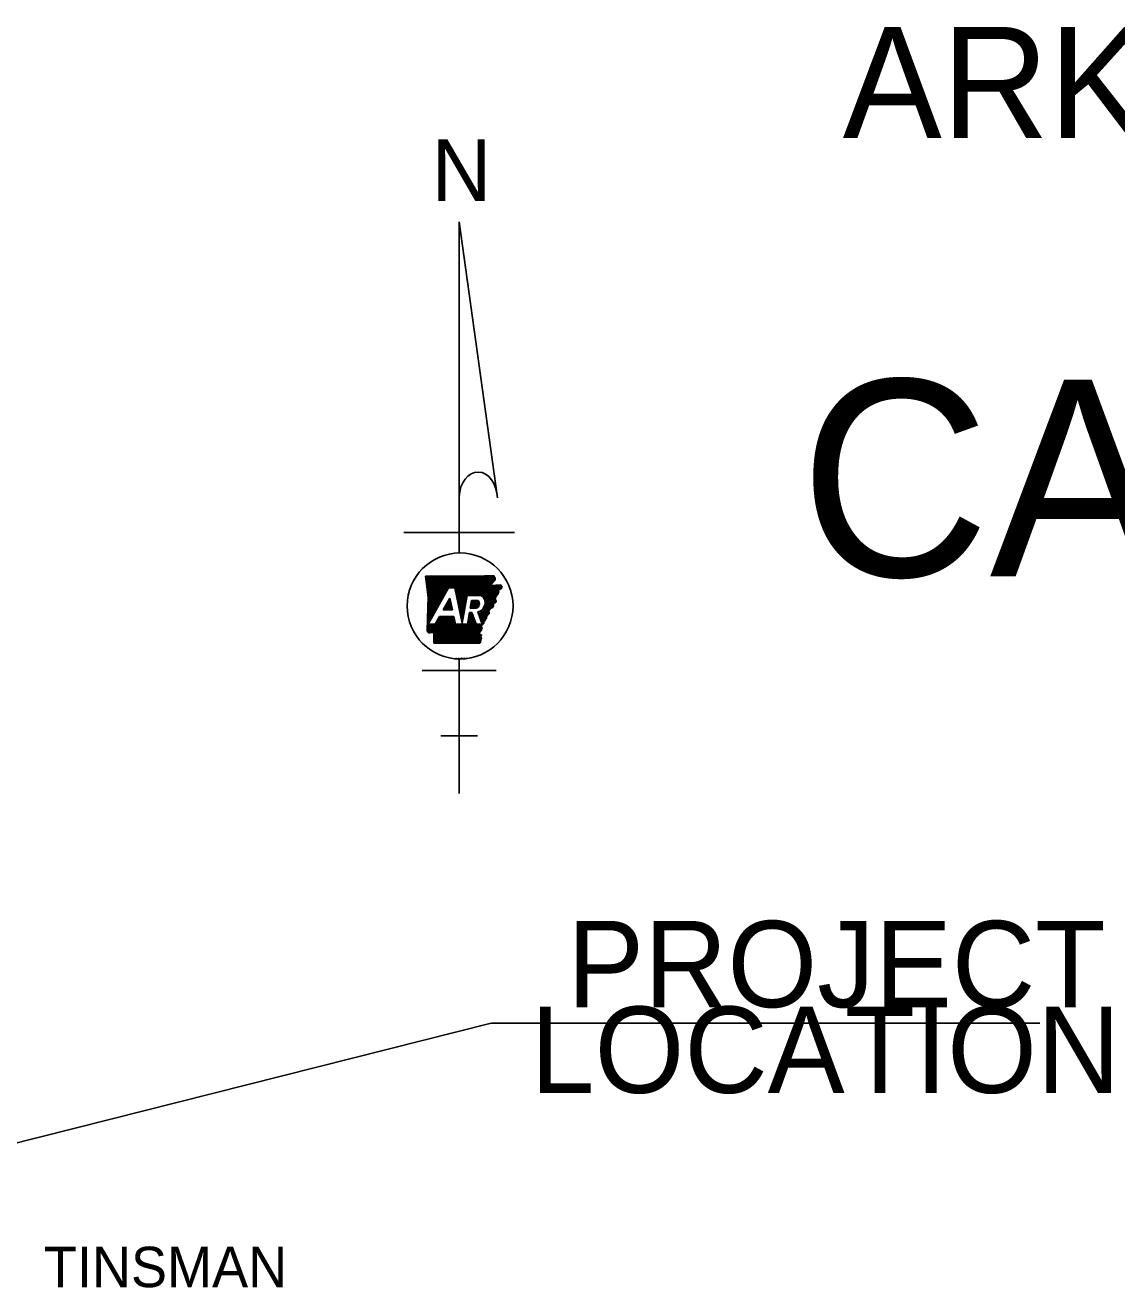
# Model space of a CAD drawing. Extents: x 172 to 3385, y 73 to 2074.
# Drawn here: x 834 to 1267, y 1573 to 2074 of the extents above; entities that cross this region are included whole.
import ezdxf

# ---------------------------------------------------------------- set-up
doc = ezdxf.new("R2010")
doc.units = 0
for name, color, linetype in [('Default', 7, 'Continuous'), ('G-ANNO-NPLT', 7, 'Continuous'), ('R_Border', 7, 'Continuous'), ('R_Border Prem', 7, 'Continuous')]:
    doc.layers.add(name, color=color, linetype=linetype)

msp = doc.modelspace()

# ---------------------------------------------------------------- linework, layer by layer
at = {"layer": 'Default'}
for p, q in [((1005.88, 1996.26), (1021.04, 1886.7)), ((1005.88, 1864.88), (1005.88, 1996.26)), ((983.94, 1873), (1027.81, 1873)), ((992.57, 1855.46), (992.75, 1855.64)), ((992.63, 1854.95), (993.33, 1855.64)), ((992.7, 1854.43), (993.91, 1855.64)), ((992.76, 1853.91), (994.49, 1855.64)), ((992.82, 1853.4), (995.07, 1855.64)), ((992.89, 1852.88), (995.65, 1855.64)), ((992.95, 1852.37), (996.23, 1855.64)), ((993.02, 1851.85), (996.81, 1855.64)), ((993.08, 1851.33), (997.39, 1855.64)), ((993.15, 1850.82), (997.97, 1855.64)), ((993.21, 1850.3), (998.55, 1855.64)), ((993.27, 1849.78), (999.13, 1855.64)), ((993.34, 1849.27), (999.71, 1855.64)), ((993.4, 1848.75), (1000.29, 1855.64)), ((993.42, 1842.96), (1006.11, 1855.65)), ((993.44, 1843.56), (1005.53, 1855.65)), ((993.46, 1844.16), (1004.95, 1855.65)), ((993.47, 1848.23), (1000.87, 1855.64)), ((993.48, 1844.76), (1004.37, 1855.65)), ((993.5, 1845.37), (1003.78, 1855.65)), ((993.52, 1845.97), (1003.2, 1855.65)), ((993.53, 1847.72), (1001.46, 1855.64)), ((993.54, 1846.57), (1002.62, 1855.64)), ((993.56, 1847.17), (1002.04, 1855.64)), ((1002.05, 1851.01), (1006.69, 1855.65)), ((1002.63, 1851.01), (1007.28, 1855.65)), ((1003.21, 1851.01), (1007.86, 1855.66)), ((1003.79, 1851.01), (1008.45, 1855.67)), ((1004.15, 1850.79), (1009.04, 1855.68)), ((1004.25, 1850.31), (1009.63, 1855.69)), ((1004.36, 1849.83), (1010.22, 1855.7)), ((1004.46, 1849.35), (1010.81, 1855.7)), ((1004.56, 1848.87), (1011.4, 1855.71)), ((1004.66, 1848.39), (1011.99, 1855.72)), ((1004.76, 1847.92), (1012.58, 1855.73)), ((1004.87, 1847.44), (1013.17, 1855.74)), ((1004.97, 1846.96), (1013.76, 1855.75)), ((1005.07, 1846.48), (1014.35, 1855.76)), ((1005.17, 1846), (1014.94, 1855.77)), ((1005.28, 1845.52), (1015.53, 1855.78)), ((1005.38, 1845.05), (1016.12, 1855.79)), ((1005.48, 1844.57), (1016.72, 1855.8)), ((1009.52, 1848.02), (1017.31, 1855.82)), ((1010.1, 1848.02), (1017.91, 1855.83)), ((1010.68, 1848.02), (1018.5, 1855.84)), ((1011.26, 1848.02), (1019.09, 1855.86)), ((1011.84, 1848.02), (1019.69, 1855.87)), ((1012.42, 1848.02), (1019.82, 1855.42)), ((1013, 1848.02), (1020.1, 1855.12)), ((1013.58, 1848.02), (1020.17, 1854.61)), ((993.38, 1841.76), (1000.48, 1848.86)), ((993.4, 1842.36), (1001.24, 1850.2)), ((993.6, 1836.7), (1001.7, 1851.01)), ((1001.7, 1851.01), (1004.1, 1851.01)), ((1008.99, 1848.02), (1014.62, 1848.02)), ((1014.16, 1848.02), (1018.85, 1852.71)), ((1014.69, 1847.97), (1018.73, 1852.01)), ((1015.01, 1847.7), (1019.35, 1852.04)), ((1015.29, 1847.41), (1019.96, 1852.08)), ((1015.54, 1847.08), (1020.57, 1852.11)), ((1015.76, 1846.71), (1021.18, 1852.14)), ((1015.93, 1846.31), (1021.8, 1852.17)), ((1016.03, 1844.08), (1021.3, 1849.35)), ((1016.07, 1845.86), (1022.35, 1852.14)), ((1016.15, 1845.36), (1022.62, 1851.83)), ((1016.15, 1844.78), (1021.23, 1849.86)), ((1020.65, 1848.12), (1021.37, 1848.84)), ((1022.36, 1850.99), (1022.89, 1851.52)), ((993.3, 1839.36), (997.45, 1843.5)), ((993.32, 1839.96), (998.21, 1844.84)), ((993.34, 1840.56), (998.96, 1846.18)), ((993.36, 1841.16), (999.72, 1847.52)), ((999.55, 1842.31), (1002.2, 1846.99)), ((999.58, 1842.31), (1002.57, 1845.3)), ((1000.16, 1842.31), (1002.67, 1844.82)), ((1000.28, 1843.59), (1002.46, 1845.78)), ((1000.74, 1842.31), (1002.77, 1844.34)), ((1001.03, 1844.93), (1002.36, 1846.26)), ((1001.33, 1842.31), (1002.87, 1843.86)), ((1001.79, 1846.27), (1002.26, 1846.73)), ((1001.91, 1842.31), (1002.98, 1843.39)), ((1002.49, 1842.31), (1003.08, 1842.91)), ((1005.58, 1844.09), (1008.88, 1847.38)), ((1005.69, 1843.61), (1008.76, 1846.68)), ((1005.79, 1843.13), (1008.63, 1845.98)), ((1005.89, 1842.65), (1008.51, 1845.27)), ((1005.99, 1842.18), (1008.39, 1844.57)), ((1006.1, 1841.7), (1008.27, 1843.87)), ((1006.2, 1841.22), (1008.14, 1843.16)), ((1010.21, 1842.95), (1013.27, 1846)), ((1010.21, 1842.95), (1012.62, 1842.95)), ((1010.33, 1843.65), (1012.69, 1846)), ((1010.46, 1844.35), (1012.11, 1846)), ((1010.58, 1845.05), (1011.53, 1846)), ((1010.7, 1845.76), (1010.95, 1846)), ((1010.74, 1846), (1013.39, 1846)), ((1010.8, 1842.95), (1013.59, 1845.74)), ((1011.38, 1842.95), (1013.79, 1845.36)), ((1011.96, 1842.95), (1013.9, 1844.89)), ((1012.54, 1842.95), (1013.85, 1844.26)), ((1013.63, 1840.52), (1020.07, 1846.96)), ((1013.79, 1840.1), (1020.18, 1846.49)), ((1013.94, 1839.67), (1020.29, 1846.01)), ((1014.1, 1839.25), (1020.39, 1845.54)), ((1015.52, 1842.99), (1019.96, 1847.43)), ((1018.41, 1842.98), (1019.22, 1843.79)), ((993.22, 1836.96), (994.42, 1838.15)), ((993.24, 1837.56), (995.17, 1839.49)), ((993.26, 1838.16), (995.93, 1840.83)), ((993.28, 1838.76), (996.69, 1842.16)), ((993.35, 1833.6), (999.45, 1839.7)), ((993.69, 1833.36), (1000.03, 1839.7)), ((994.11, 1833.2), (1000.61, 1839.7)), ((994.8, 1833.31), (1001.2, 1839.7)), ((995.39, 1833.32), (1001.78, 1839.7)), ((995.85, 1833.19), (1002.36, 1839.7)), ((995.87, 1832.05), (1003.52, 1839.7)), ((995.87, 1832.63), (1002.94, 1839.7)), ((995.87, 1831.47), (1003.82, 1839.43)), ((995.87, 1830.89), (1003.93, 1838.95)), ((995.87, 1830.31), (1004.03, 1838.47)), ((995.87, 1829.73), (1004.13, 1837.99)), ((998.07, 1839.7), (996.37, 1836.7)), ((997.03, 1837.86), (998.87, 1839.7)), ((997.79, 1839.2), (998.29, 1839.7)), ((1003.77, 1839.7), (998.07, 1839.7)), ((999.55, 1842.31), (1003.21, 1842.31)), ((1001.68, 1829.15), (1011.67, 1839.14)), ((1002.26, 1829.15), (1011.83, 1838.72)), ((1002.84, 1829.15), (1011.98, 1838.29)), ((1003.07, 1842.31), (1003.18, 1842.43)), ((1006.3, 1840.74), (1008.02, 1842.46)), ((1006.4, 1840.26), (1007.9, 1841.76)), ((1006.51, 1839.78), (1007.78, 1841.06)), ((1006.61, 1839.31), (1007.65, 1840.35)), ((1006.71, 1838.83), (1007.53, 1839.65)), ((1006.81, 1838.35), (1007.41, 1838.95)), ((1006.91, 1837.87), (1007.29, 1838.24)), ((1009.22, 1837.28), (1011.51, 1839.56)), ((1009.35, 1837.98), (1011.36, 1839.99)), ((1009.47, 1838.68), (1011.2, 1840.41)), ((1009.59, 1839.39), (1011.04, 1840.84)), ((1009.71, 1840.09), (1010.87, 1841.25)), ((1009.84, 1840.79), (1010.29, 1841.25)), ((1010.89, 1841.25), (1009.92, 1841.25)), ((1012.57, 1836.7), (1010.89, 1841.25)), ((1013.27, 1841.49), (1015.04, 1836.7)), ((1013.32, 1841.37), (1013.49, 1841.55)), ((1013.47, 1840.95), (1014.58, 1842.05)), ((1014.26, 1838.82), (1017.74, 1842.31)), ((1014.41, 1838.4), (1017.68, 1841.66)), ((1014.57, 1837.98), (1017.61, 1841.02)), ((1014.73, 1837.55), (1016.51, 1839.33)), ((1014.88, 1837.13), (1016.26, 1838.5)), ((993.13, 1833.96), (995.87, 1836.7)), ((993.14, 1834.55), (995.29, 1836.7)), ((993.16, 1835.15), (994.71, 1836.7)), ((993.18, 1835.75), (994.13, 1836.7)), ((993.2, 1836.36), (993.66, 1836.81)), ((996.37, 1836.7), (993.6, 1836.7)), ((995.88, 1829.16), (1004.23, 1837.51)), ((996.46, 1829.16), (1004.34, 1837.03)), ((997.04, 1829.16), (1004.58, 1836.7)), ((997.62, 1829.16), (1005.16, 1836.7)), ((998.2, 1829.16), (1005.74, 1836.7)), ((998.78, 1829.16), (1006.32, 1836.7)), ((999.36, 1829.16), (1006.9, 1836.7)), ((999.94, 1829.16), (1007.49, 1836.7)), ((1000.52, 1829.15), (1008.07, 1836.7)), ((1001.1, 1829.15), (1008.65, 1836.7)), ((1003.42, 1829.15), (1012.14, 1837.87)), ((1004, 1829.15), (1012.3, 1837.44)), ((1009.12, 1836.7), (1004.41, 1836.7)), ((1004.58, 1829.15), (1012.45, 1837.02)), ((1005.16, 1829.15), (1012.71, 1836.7)), ((1005.74, 1829.15), (1013.29, 1836.7)), ((1006.32, 1829.14), (1013.87, 1836.7)), ((1006.9, 1829.14), (1014.45, 1836.7)), ((1007.02, 1837.39), (1007.16, 1837.54)), ((1007.48, 1829.14), (1014.65, 1836.31)), ((1008.06, 1829.14), (1014.67, 1835.76)), ((1008.64, 1829.14), (1014.7, 1835.2)), ((1009.22, 1829.14), (1014.73, 1834.65)), ((1009.8, 1829.14), (1013.77, 1833.11)), ((1015.04, 1836.7), (1012.57, 1836.7)), ((1010.38, 1829.14), (1013.95, 1832.71)), ((1010.96, 1829.14), (1014.13, 1832.31)), ((1011.54, 1829.14), (1014.31, 1831.91)), ((1012.12, 1829.14), (1014.49, 1831.51)), ((1012.7, 1829.13), (1014.64, 1831.08)), ((1013.28, 1829.13), (1014.38, 1830.23)), ((1013.86, 1829.13), (1014.11, 1829.39)), ((991.25, 1818.32), (1020.5, 1818.32)), ((1005.88, 1769.53), (1005.88, 1822.85)), ((998.56, 1792.34), (1013.19, 1792.34))]:
    msp.add_line(p, q, dxfattribs=at)
for points in [[(992.54, 1855.64), (1000.55, 1855.64), (1007.59, 1855.66), (1015.88, 1855.78), (1019.73, 1855.87)], [(992.54, 1855.64), (1000.56, 1855.64), (1007.59, 1855.65), (1015.88, 1855.78), (1019.73, 1855.87)], [(993.43, 1843.19), (993.57, 1847.41), (992.54, 1855.64)], [(993.12, 1833.97), (993.57, 1847.41), (992.54, 1855.64)], [(1004.1, 1851.01), (1007.08, 1837.08), (1008.99, 1848.02)], [(1022.24, 1852.19), (1022.94, 1851.47), (1021.21, 1850.05), (1021.39, 1848.61), (1019.91, 1847.63), (1020.42, 1845.43), (1019.28, 1844.39), (1019.18, 1843.25), (1017.79, 1842.75), (1017.57, 1840.61), (1016.57, 1839.55), (1016.09, 1837.93), (1014.63, 1836.6), (1014.74, 1834.26), (1013.76, 1833.15), (1014.66, 1831.13), (1014.03, 1829.13)], [(1018.54, 1852.01), (1022.3, 1852.2)], [(1018.54, 1852), (1022.3, 1852.2)], [(993.13, 1833.97), (993.43, 1843.19)], [(1002.2, 1846.99), (1003.21, 1842.31)], [(1010.21, 1842.95), (1010.74, 1846)], [(1004.41, 1836.7), (1003.77, 1839.7)], [(1009.92, 1841.25), (1009.12, 1836.7)], [(1014.03, 1829.13), (995.87, 1829.16), (995.86, 1833.17)], [(1014.03, 1829.13), (995.87, 1829.16), (995.87, 1833.17)]]:
    msp.add_lwpolyline(points, dxfattribs=at)
for centre, major_axis, ratio, start_param, end_param in [((1013.45, 1886.46), (-0.32, 10.53), 0.719778, 4.712385, 7.768526), ((1012.52, 1845.05), (-3.63, 0), 0.999987, 1.777838, 4.099264), ((1012.05, 1844.71), (-1.86, 0), 0.999987, 1.887169, 3.90762)]:
    msp.add_ellipse(centre, major_axis=major_axis, ratio=ratio, start_param=start_param, end_param=end_param, dxfattribs=at)
msp.add_ellipse((1006.22, 1843.86), major_axis=(21.02, 0), ratio=0.999976, dxfattribs=at)
for points in [[(1019.73, 1855.87), (1019.75, 1855.66), (1019.82, 1855.54), (1019.83, 1855.33), (1019.91, 1855.24), (1020.06, 1855.15), (1020.18, 1855.01), (1020.22, 1854.84), (1020.18, 1854.67), (1020.17, 1854.47), (1020.15, 1854.3), (1020.11, 1854.15), (1020, 1854.03), (1019.89, 1853.94), (1019.78, 1853.84), (1019.71, 1853.73), (1019.58, 1853.61), (1019.45, 1853.48), (1019.34, 1853.38), (1019.24, 1853.24), (1019.19, 1853.08), (1019.08, 1852.97), (1018.99, 1852.87), (1018.87, 1852.74), (1018.81, 1852.61), (1018.7, 1852.45), (1018.67, 1852.31), (1018.6, 1852.19), (1018.59, 1852.17)], [(1019.73, 1855.87), (1019.75, 1855.65), (1019.82, 1855.54), (1019.83, 1855.33), (1019.91, 1855.24), (1020.06, 1855.15), (1020.19, 1855.01), (1020.22, 1854.84), (1020.18, 1854.67), (1020.17, 1854.48), (1020.15, 1854.31), (1020.12, 1854.15), (1020, 1854.03), (1019.89, 1853.94), (1019.78, 1853.84), (1019.71, 1853.73), (1019.58, 1853.61), (1019.45, 1853.48), (1019.35, 1853.38), (1019.24, 1853.24), (1019.19, 1853.08), (1019.08, 1852.97), (1018.99, 1852.88), (1018.87, 1852.74), (1018.81, 1852.61), (1018.7, 1852.45), (1018.67, 1852.31), (1018.6, 1852.19), (1018.59, 1852.17)], [(1022.24, 1852.19), (1022.3, 1852.2), (1022.46, 1852.02), (1022.54, 1851.87), (1022.65, 1851.79), (1022.78, 1851.74), (1022.87, 1851.63), (1022.93, 1851.5), (1022.9, 1851.39), (1022.76, 1851.38), (1022.6, 1851.36), (1022.46, 1851.36), (1022.33, 1851.26), (1022.45, 1851.13), (1022.59, 1851), (1022.63, 1850.87), (1022.55, 1850.75), (1022.39, 1850.67), (1022.24, 1850.61), (1022.1, 1850.5), (1022.03, 1850.38), (1021.88, 1850.33), (1021.72, 1850.29), (1021.58, 1850.27), (1021.43, 1850.24), (1021.27, 1850.17), (1021.21, 1850.04), (1021.23, 1849.86), (1021.22, 1849.67), (1021.38, 1849.6), (1021.53, 1849.59), (1021.67, 1849.52), (1021.65, 1849.41), (1021.55, 1849.27), (1021.43, 1849.16), (1021.3, 1849.11), (1021.19, 1849), (1021.23, 1848.9), (1021.33, 1848.83), (1021.41, 1848.72), (1021.4, 1848.62), (1021.28, 1848.54), (1021.15, 1848.57), (1021.05, 1848.69), (1020.95, 1848.73), (1020.85, 1848.78), (1020.74, 1848.71), (1020.74, 1848.57), (1020.7, 1848.42), (1020.74, 1848.3), (1020.78, 1848.14), (1020.77, 1848.03), (1020.74, 1847.86), (1020.65, 1847.68), (1020.56, 1847.63), (1020.51, 1847.82), (1020.49, 1847.97), (1020.43, 1848.06), (1020.35, 1848.06), (1020.25, 1847.99), (1020.14, 1847.88), (1020, 1847.75), (1019.91, 1847.63), (1019.96, 1847.48), (1020.06, 1847.44), (1020.15, 1847.46), (1020.19, 1847.56), (1020.27, 1847.58), (1020.35, 1847.42)], [(1020.35, 1847.42), (1020.38, 1847.28), (1020.29, 1847.13), (1020.26, 1846.98), (1020.27, 1846.82), (1020.11, 1846.74), (1019.98, 1846.64), (1020.06, 1846.52), (1020.21, 1846.41), (1020.35, 1846.33), (1020.45, 1846.24), (1020.47, 1846.04), (1020.5, 1845.91), (1020.55, 1845.73), (1020.57, 1845.61), (1020.48, 1845.46), (1020.38, 1845.43), (1020.26, 1845.46), (1020.14, 1845.47), (1020.03, 1845.38), (1019.96, 1845.23), (1019.89, 1845.1), (1019.83, 1844.98), (1019.77, 1844.85), (1019.67, 1844.7), (1019.53, 1844.68), (1019.37, 1844.63), (1019.28, 1844.53), (1019.3, 1844.34), (1019.39, 1844.22), (1019.45, 1844.07), (1019.5, 1843.93), (1019.48, 1843.76), (1019.41, 1843.64), (1019.32, 1843.56), (1019.28, 1843.41), (1019.21, 1843.29), (1019.16, 1843.25), (1019.04, 1843.26), (1018.91, 1843.28), (1018.8, 1843.27), (1018.7, 1843.22), (1018.59, 1843.25), (1018.48, 1843.37), (1018.39, 1843.46), (1018.29, 1843.5), (1018.19, 1843.44), (1018.17, 1843.28), (1018.22, 1843.11), (1018.26, 1842.88), (1018.22, 1842.74), (1018.2, 1842.51)], [(1018.2, 1842.51), (1018.03, 1842.38), (1017.95, 1842.25), (1017.51, 1842.29), (1017.53, 1842.13), (1017.37, 1842.05), (1017.23, 1841.95), (1017.31, 1841.83), (1017.46, 1841.72), (1017.61, 1841.64), (1017.7, 1841.55), (1017.72, 1841.35), (1017.75, 1841.22), (1017.8, 1841.04), (1017.82, 1840.92), (1017.73, 1840.77), (1017.62, 1840.74), (1017.52, 1840.78), (1017.39, 1840.78), (1017.29, 1840.69), (1017.21, 1840.55), (1017.14, 1840.41), (1017.08, 1840.29), (1017.02, 1840.16), (1016.92, 1840.01), (1016.79, 1839.99), (1016.63, 1839.95), (1016.53, 1839.84), (1016.55, 1839.65), (1016.64, 1839.53), (1016.71, 1839.38), (1016.75, 1839.24), (1016.73, 1839.08), (1016.66, 1838.95), (1016.57, 1838.87), (1016.53, 1838.72), (1016.47, 1838.6), (1016.41, 1838.56), (1016.29, 1838.57), (1016.16, 1838.59), (1016.05, 1838.58), (1015.95, 1838.53), (1015.84, 1838.57), (1015.73, 1838.68), (1015.64, 1838.77), (1015.55, 1838.81), (1015.44, 1838.75), (1015.42, 1838.59), (1015.47, 1838.42), (1015.52, 1838.19), (1015.47, 1838.06), (1015.46, 1837.82)], [(995.86, 1833.17), (995.88, 1833.16), (995.79, 1833.22), (995.66, 1833.29), (995.52, 1833.3), (995.33, 1833.32), (995.18, 1833.34), (995.02, 1833.44), (994.85, 1833.33), (994.67, 1833.25), (994.56, 1833.34), (994.41, 1833.28), (994.31, 1833.31), (994.14, 1833.2), (993.98, 1833.24), (993.86, 1833.2), (993.71, 1833.21), (993.68, 1833.38), (993.54, 1833.4), (993.41, 1833.47), (993.33, 1833.65), (993.27, 1833.78), (993.12, 1833.97)], [(995.87, 1833.17), (995.89, 1833.16), (995.79, 1833.23), (995.66, 1833.29), (995.52, 1833.3), (995.33, 1833.32), (995.18, 1833.34), (995.02, 1833.44), (994.86, 1833.34), (994.67, 1833.25), (994.56, 1833.35), (994.41, 1833.28), (994.31, 1833.32), (994.14, 1833.19), (993.97, 1833.24), (993.86, 1833.21), (993.71, 1833.21), (993.68, 1833.38), (993.53, 1833.4), (993.41, 1833.47), (993.33, 1833.64), (993.27, 1833.78), (993.13, 1833.97)], [(1014.79, 1835.96), (1014.74, 1835.84), (1014.69, 1835.65), (1014.7, 1835.48), (1014.78, 1835.34), (1014.89, 1835.26), (1015.03, 1835.14), (1015.02, 1834.97), (1014.94, 1834.91), (1014.76, 1834.95), (1014.63, 1835.01), (1014.52, 1834.97), (1014.37, 1834.9), (1014.25, 1834.88), (1014.26, 1834.65), (1014.41, 1834.48), (1014.54, 1834.48), (1014.7, 1834.46), (1014.75, 1834.28), (1014.66, 1834.13), (1014.51, 1834.06), (1014.33, 1834.15), (1014.19, 1834.24), (1014.06, 1834.33), (1013.89, 1834.37), (1013.79, 1834.36), (1013.75, 1834.15), (1013.83, 1833.96), (1013.96, 1833.83), (1014.08, 1833.66), (1014.06, 1833.53), (1013.97, 1833.5), (1013.81, 1833.47), (1013.72, 1833.42), (1013.69, 1833.38), (1013.74, 1833.21), (1013.78, 1833.03), (1013.78, 1832.89), (1013.73, 1832.76), (1013.65, 1832.56), (1013.66, 1832.44), (1013.72, 1832.37), (1013.79, 1832.39), (1013.89, 1832.46), (1013.95, 1832.54), (1014.01, 1832.64), (1014.11, 1832.72), (1014.24, 1832.65), (1014.27, 1832.5), (1014.2, 1832.36), (1014.09, 1832.3), (1013.97, 1832.25), (1013.87, 1832.15), (1013.89, 1832.01), (1013.97, 1831.95), (1014.15, 1831.98), (1014.27, 1832.04), (1014.35, 1832.1), (1014.43, 1832.19), (1014.47, 1832.28), (1014.54, 1832.36), (1014.65, 1832.39), (1014.71, 1832.32), (1014.69, 1832.15), (1014.62, 1831.98), (1014.52, 1831.85), (1014.42, 1831.76), (1014.29, 1831.56), (1014.32, 1831.37), (1014.37, 1831.21), (1014.43, 1831.09), (1014.55, 1831.12), (1014.69, 1831.13), (1014.76, 1831.07), (1014.76, 1830.93), (1014.66, 1830.79), (1014.56, 1830.67), (1014.51, 1830.49), (1014.53, 1830.36), (1014.53, 1830.25), (1014.49, 1830.13), (1014.43, 1830.06), (1014.24, 1830.06), (1014.05, 1830.08), (1013.95, 1830.02), (1013.97, 1829.86), (1014.08, 1829.73), (1014.16, 1829.67), (1014.27, 1829.53), (1014.32, 1829.41), (1014.31, 1829.32), (1014.23, 1829.23), (1014.03, 1829.13)], [(1014.79, 1835.96), (1014.74, 1835.84), (1014.69, 1835.65), (1014.7, 1835.48), (1014.78, 1835.34), (1014.89, 1835.26), (1015.03, 1835.14), (1015.02, 1834.97), (1014.94, 1834.91), (1014.76, 1834.95), (1014.63, 1835.01), (1014.52, 1834.97), (1014.37, 1834.9), (1014.25, 1834.88), (1014.26, 1834.65), (1014.41, 1834.48), (1014.54, 1834.48), (1014.7, 1834.46), (1014.75, 1834.28), (1014.66, 1834.13), (1014.51, 1834.06), (1014.33, 1834.15), (1014.19, 1834.24), (1014.06, 1834.33), (1013.89, 1834.37), (1013.79, 1834.36), (1013.75, 1834.15), (1013.83, 1833.96), (1013.96, 1833.83), (1014.08, 1833.66), (1014.06, 1833.53), (1013.97, 1833.5), (1013.81, 1833.47), (1013.72, 1833.42), (1013.69, 1833.38), (1013.74, 1833.21), (1013.78, 1833.03), (1013.78, 1832.89), (1013.73, 1832.76), (1013.65, 1832.56), (1013.66, 1832.44), (1013.72, 1832.37), (1013.79, 1832.39), (1013.89, 1832.46), (1013.95, 1832.54), (1014.01, 1832.64), (1014.11, 1832.72), (1014.24, 1832.65), (1014.27, 1832.5), (1014.2, 1832.36), (1014.09, 1832.3), (1013.97, 1832.25), (1013.87, 1832.15), (1013.89, 1832.01), (1013.97, 1831.95), (1014.15, 1831.98), (1014.27, 1832.04), (1014.35, 1832.1), (1014.43, 1832.19), (1014.47, 1832.28), (1014.54, 1832.36), (1014.65, 1832.39), (1014.71, 1832.32), (1014.69, 1832.15), (1014.62, 1831.98), (1014.52, 1831.85), (1014.42, 1831.76), (1014.29, 1831.56), (1014.32, 1831.37), (1014.37, 1831.21), (1014.43, 1831.09), (1014.55, 1831.12), (1014.69, 1831.13), (1014.76, 1831.07), (1014.76, 1830.93), (1014.66, 1830.79), (1014.56, 1830.67), (1014.51, 1830.49), (1014.53, 1830.36), (1014.53, 1830.25), (1014.49, 1830.13), (1014.43, 1830.06), (1014.24, 1830.06), (1014.05, 1830.08), (1013.95, 1830.02), (1013.97, 1829.86), (1014.08, 1829.73), (1014.16, 1829.67), (1014.27, 1829.53), (1014.32, 1829.41), (1014.31, 1829.32), (1014.23, 1829.23), (1014.03, 1829.13)], [(1015.46, 1837.82), (1015.45, 1837.82), (1015.36, 1837.71), (1015.41, 1837.53), (1015.6, 1837.46), (1015.69, 1837.29), (1015.69, 1837.15), (1015.63, 1836.94), (1015.54, 1836.85), (1015.37, 1836.81), (1015.23, 1836.78), (1015.21, 1836.55), (1015.15, 1836.44), (1015.05, 1836.41), (1014.9, 1836.48), (1014.81, 1836.52), (1014.7, 1836.57), (1014.56, 1836.65), (1014.46, 1836.63), (1014.49, 1836.42), (1014.5, 1836.41), (1014.62, 1836.24), (1014.73, 1836.11), (1014.79, 1835.96)], [(1015.46, 1837.82), (1015.45, 1837.82), (1015.36, 1837.71), (1015.41, 1837.53), (1015.6, 1837.46), (1015.69, 1837.29), (1015.69, 1837.15), (1015.63, 1836.94), (1015.54, 1836.85), (1015.37, 1836.81), (1015.23, 1836.78), (1015.21, 1836.55), (1015.15, 1836.44), (1015.05, 1836.41), (1014.9, 1836.48), (1014.81, 1836.52), (1014.7, 1836.57), (1014.56, 1836.65), (1014.46, 1836.63), (1014.49, 1836.42), (1014.5, 1836.41), (1014.62, 1836.24), (1014.73, 1836.11), (1014.79, 1835.96)]]:
    msp.add_spline(points, degree=3, dxfattribs=at)
at = {"layer": 'R_Border Prem'}
msp.add_lwpolyline([(603.86, 1573.8), (1018.61, 1678.41), (1236.26, 1678.41)], dxfattribs=at)

# ---------------------------------------------------------------- texts
at = {"layer": 'Default'}
for s, height, p in [('N', 24.45, (994.98, 2004.52)), ('STS 10-03-17', 0.6076, (1004.21, 1823.02))]:
    msp.add_text(s, height=height, dxfattribs=at).set_placement(p)
at = {"layer": 'G-ANNO-NPLT'}
msp.add_text('TINSMAN', height=16.04, dxfattribs=at).set_placement((841.09, 1573.65))
at = {"layer": 'R_Border'}
for s, height, p in [('ARKANSAS DEPARTMENT OF TRANSPORTATION', 44.0283, (1158.09, 2029.52)), ('CANEY & TAYLOR CREEK', 78, (1141.07, 1855.58)), ('PROJECT', 34.24, (1048.71, 1684.71)), ('LOCATION', 34.24, (1034.15, 1650.71))]:
    msp.add_text(s, height=height, dxfattribs=at).set_placement(p)

doc.saveas('drawing.dxf')
